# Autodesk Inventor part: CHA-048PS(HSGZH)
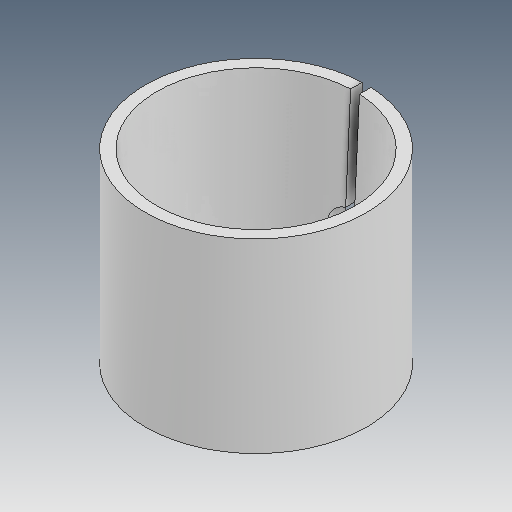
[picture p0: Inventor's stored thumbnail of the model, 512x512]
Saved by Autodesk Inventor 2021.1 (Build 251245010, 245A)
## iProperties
Created: 2021-05
Part Number: CHA-048PS(HSGZH)
Material: Ogólny
Document SubType Name: Modeling
Designer: user
Density: 1 g/cm^3
Appearance: Domyślna
Author: user
Revision Number: ÈÎºÎ
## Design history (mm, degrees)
feature "ÇÐ³ý-À­Éì2"
node "Bryła1"
